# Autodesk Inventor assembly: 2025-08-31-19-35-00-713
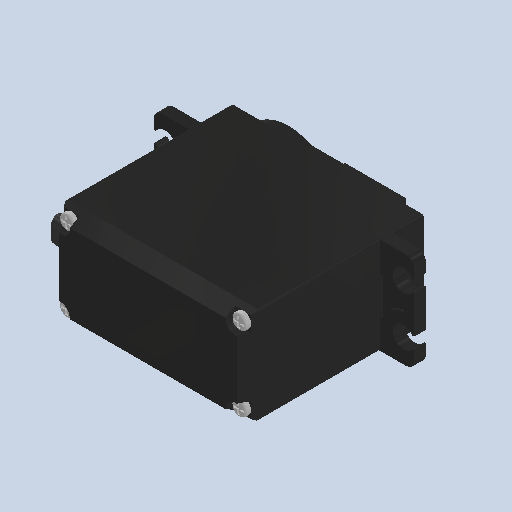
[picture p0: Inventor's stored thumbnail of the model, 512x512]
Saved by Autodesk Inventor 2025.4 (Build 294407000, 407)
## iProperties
Created: 2026-09
Part Number: 2025-08-31-19-35-00-713
Document SubType Name: Assembly
Designer: AdminForWorker
Title: MG995 v1
Author: AdminForWorker
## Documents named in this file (2)
- c:\worker\convert-fusion-r05-cosv3\tmp\job-1\19\temp\files\ca3d996b-dda0-445d-8bee-12a194174ca8\MG995 v1.iam
- c:\worker\convert-fusion-r05-cosv3\tmp\job-1\19\temp\files\ca3d996b-dda0-445d-8bee-12a194174ca8\Servo.iam
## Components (1 placed, 1 different names)
1. Servo:1 [sub-assembly]
